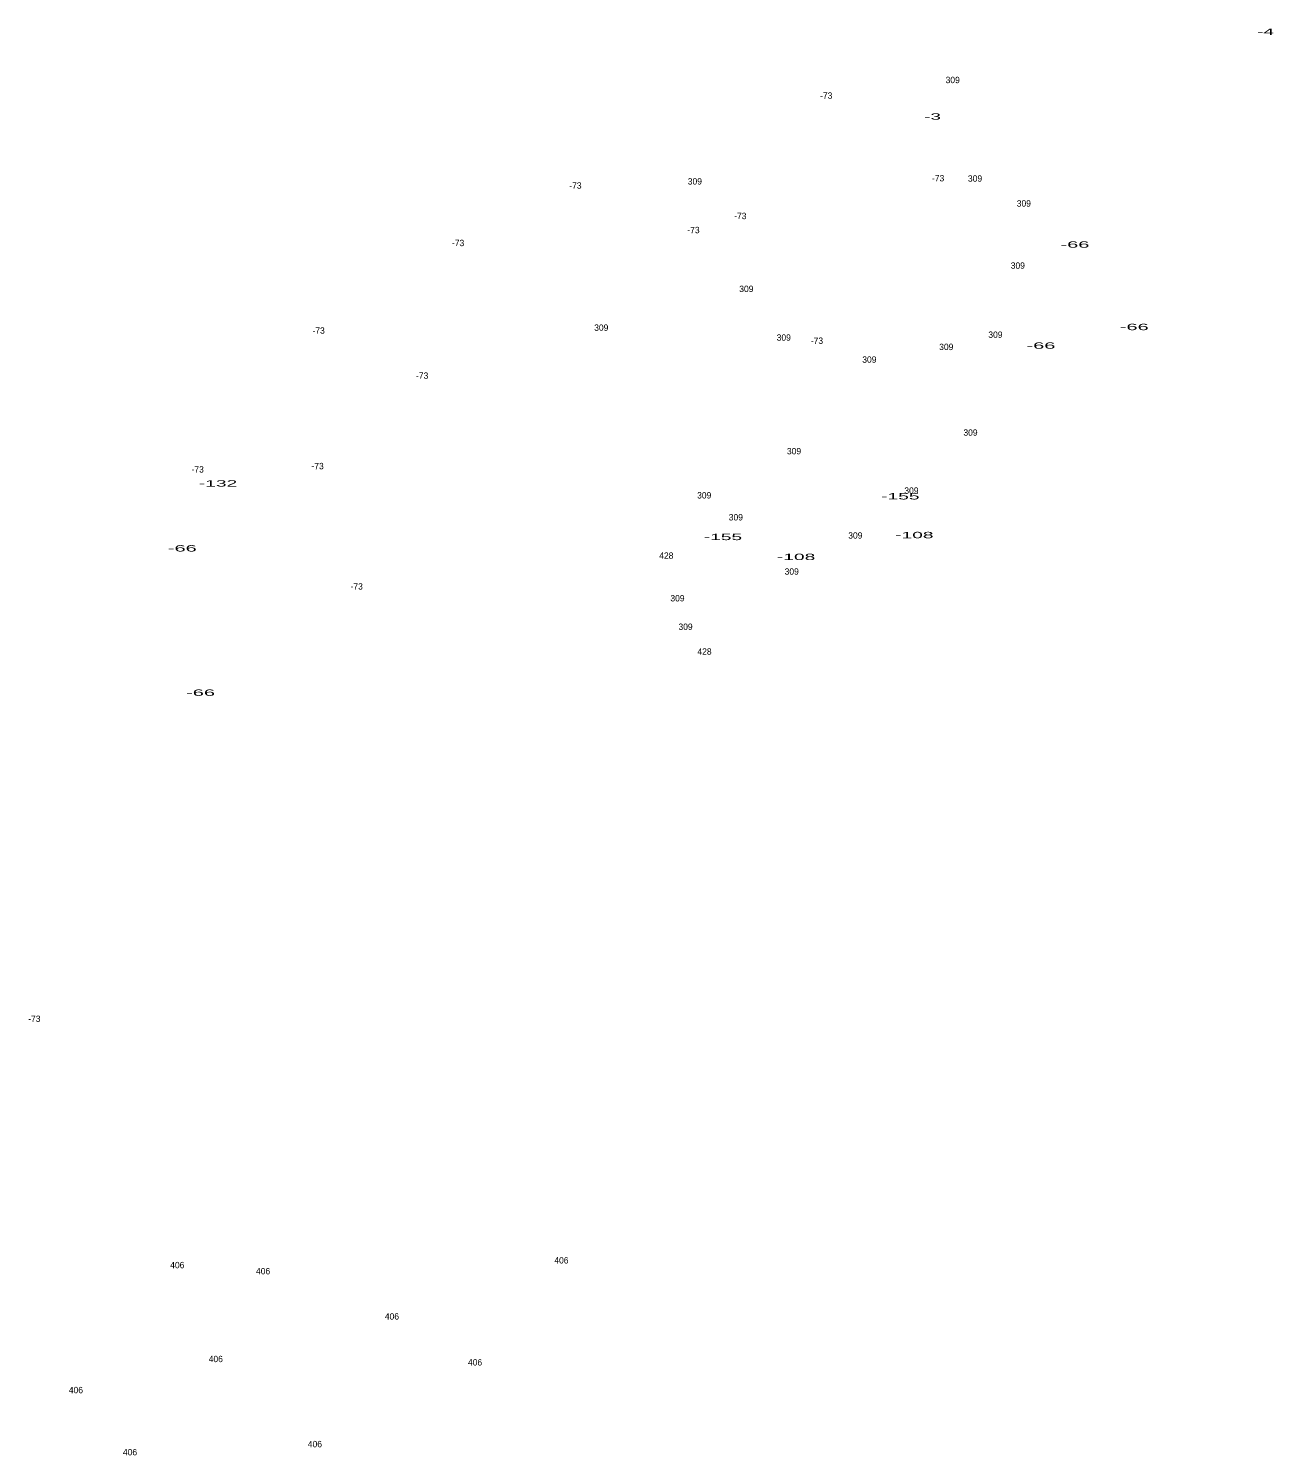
# Model space of a CAD drawing. Extents: x -662280 to -658689, y -991723 to -987042.
# Drawn here: x -659539 to -658756, y -989252 to -988355 of the extents above; entities that cross this region are included whole.
import ezdxf
from ezdxf.enums import TextEntityAlignment as Align

# ---------------------------------------------------------------- set-up
doc = ezdxf.new("R2010")
doc.units = 0
doc.header["$LTSCALE"] = 1.6
doc.layers.add('24', color=7, linetype='Continuous')

msp = doc.modelspace()

# ---------------------------------------------------------------- texts
at = {"layer": '24'}
for s, width, p in [('-4', 2.25, (-658761.37, -988358.51)), ('-3', 2.2, (-658970.734, -988411.83)), ('-3', 2.2, (-658970.734, -988411.83)), ('-66', 2.35, (-658881.223, -988492.38)), ('-66', 2.35, (-658843.913, -988544.23)), ('-66', 2.35, (-658902.593, -988555.94)), ('-132', 2.25, (-659420.131, -988642.61)), ('-155', 2.25, (-658991.001, -988650.73)), ('-108', 2.25, (-658982.227, -988675.12)), ('-66', 2.35, (-659442.613, -988683.47)), ('-155', 2.25, (-659102.591, -988676.31)), ('-108', 2.25, (-659056.577, -988688.86)), ('-66', 2.35, (-659431.123, -988774.26))]:
    msp.add_text(s, height=4, dxfattribs=dict(at, width=width)).set_placement(p, align=Align.CENTER)
for s, p in [('309', (-658958.097, -988388.86)), ('-73', (-659037.641, -988398.65)), ('-73', (-658967.261, -988450.64)), ('309', (-658944.047, -988450.82)), ('-73', (-659195.371, -988455.26)), ('309', (-659120.257, -988452.63)), ('309', (-658913.357, -988466.54)), ('-73', (-659091.681, -988474.41)), ('-73', (-659121.121, -988483.26)), ('-73', (-659121.121, -988483.26)), ('-73', (-659269.171, -988491.38)), ('309', (-658917.137, -988505.61)), ('309', (-659087.877, -988520.27)), ('-73', (-659356.881, -988546.46)), ('309', (-659179.117, -988544.66)), ('309', (-658931.227, -988549.09)), ('309', (-659064.327, -988550.88)), ('-73', (-659043.481, -988552.87)), ('309', (-658962.147, -988556.77)), ('309', (-659010.507, -988564.76)), ('-73', (-659291.791, -988574.83)), ('309', (-658946.907, -988610.65)), ('309', (-659057.897, -988622.31)), ('-73', (-659432.941, -988633.8)), ('-73', (-659357.531, -988631.73)), ('309', (-658984.057, -988647.16)), ('309', (-659114.367, -988650.12)), ('309', (-659094.477, -988663.94)), ('309', (-659019.337, -988675.35)), ('428', (-659138.201, -988688.05)), ('309', (-659059.327, -988698.04)), ('-73', (-659332.931, -988707.39)), ('309', (-659131.187, -988714.87)), ('309', (-659126.117, -988732.79)), ('428', (-659114.191, -988748.39)), ('-73', (-659535.691, -988979.39)), ('406', (-659204.191, -989131.34)), ('406', (-659445.771, -989134.32)), ('406', (-659391.801, -989138.14)), ('406', (-659310.771, -989166.62)), ('406', (-659421.551, -989193.39)), ('406', (-659258.501, -989195.51)), ('406', (-659509.511, -989212.94)), ('406', (-659359.211, -989246.93)), ('406', (-659475.521, -989252.03))]:
    msp.add_text(s, height=4, dxfattribs=at).set_placement(p, align=Align.CENTER)

doc.saveas('drawing.dxf')
